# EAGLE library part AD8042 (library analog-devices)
Dual 160 MHz Rail-to-Rail Amplifier Source: http://www.analog.com/static/imported-files/data_sheets/AD8042.pdf
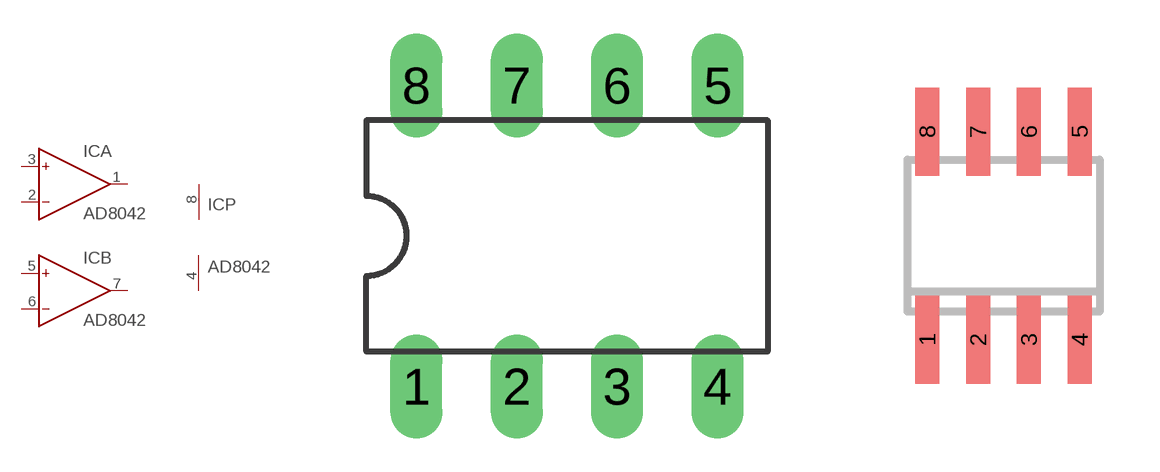
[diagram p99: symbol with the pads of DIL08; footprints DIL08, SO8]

Designator prefix IC; gates A=OP B=OP P=PWR+-

## AD8042N (MF: ANALOG DEVICES; MPN: AD8042AN; OC_FARNELL: 1540543; OC_NEWARK: 52F8033)  [DIL08]
1  A:OUT  out
2  A:IN-  in
3  A:IN+  in
4  P:V-  pwr
5  B:IN+  in
6  B:IN-  in
7  B:OUT  out
8  P:V+  pwr

## AD8042R (MF: ALTERA CORPORATION; MPN: AD8042AR; OC_FARNELL: 1424032; OC_NEWARK: 52F8034)  [SO8]
Pads as for DIL08

## Footprint DIL08 (pad centres in mm)
Dual In Line Package
drill 0.813 long: 1 -3.81,-3.81; 2 -1.27,-3.81; 3 1.27,-3.81; 4 3.81,-3.81; 5 3.81,3.81; 6 1.27,3.81; 7 -1.27,3.81; 8 -3.81,3.81

## Footprint SO8 (pad centres in mm)
8-Lead Small Outline IC (SO-8) Source: http://www.analog.com/UploadedFiles/Data_Sheets/703465986AD8611_2_0.pdf
smd 0.6 x 2.2: 1 -1.905,-2.6; 2 -0.635,-2.6; 3 0.635,-2.6; 4 1.905,-2.6; 5 1.905,2.6; 6 0.635,2.6; 7 -0.635,2.6; 8 -1.905,2.6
